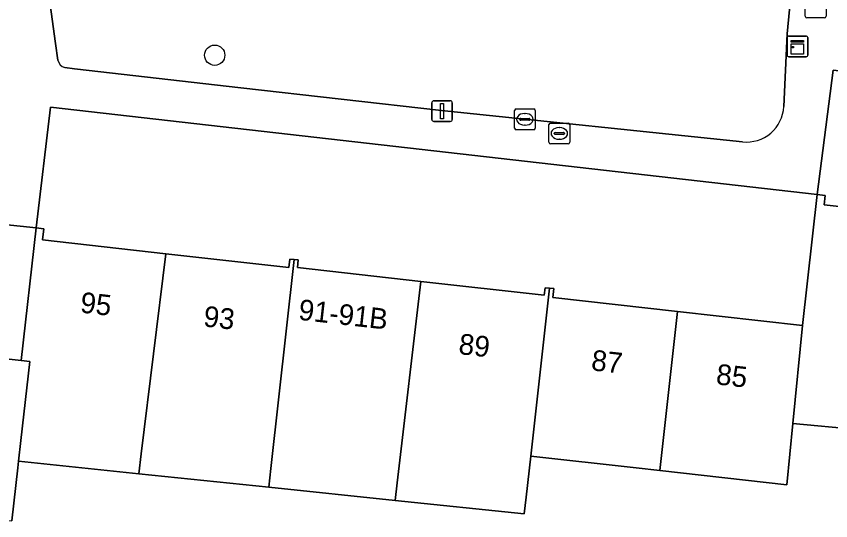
# Model space of a CAD drawing. Extents: x 162026 to 163502, y 387295 to 388169.
# Drawn here: x 162441.8 to 162481.07, y 387497.45 to 387521.8 of the extents above; entities that cross this region are included whole.
import ezdxf

# ---------------------------------------------------------------- set-up
doc = ezdxf.new("R2010")
doc.units = 0
for name, color, linetype in [('IMGEO_Boom', 7, 'Continuous'), ('IMGEO_Brandkraan', 7, 'Continuous'), ('IMGEO_Erf', 7, 'Continuous'), ('IMGEO_Groenvoorziening', 7, 'Continuous'), ('IMGEO_Kast', 7, 'Continuous'), ('IMGEO_Kolk', 7, 'Continuous'), ('IMGEO_Lichtmast', 7, 'Continuous'), ('IMGEO_Pand', 7, 'Continuous'), ('IMGEO_Pand_nummerreeks', 7, 'Continuous'), ('IMGEO_Rioolput', 7, 'Continuous'), ('IMGEO_Voetpad_open', 7, 'Continuous')]:
    doc.layers.add(name, color=color, linetype=linetype)

msp = doc.modelspace()

# ---------------------------------------------------------------- linework, layer by layer
at = {"layer": 'IMGEO_Boom'}
msp.add_circle((162451.365, 387519.921), 0.489, dxfattribs=at)
at = {"layer": 'IMGEO_Brandkraan'}
for p, q in [((162467.56, 387516.645), (162468.412, 387516.645)), ((162467.485, 387515.719), (162467.485, 387516.571)), ((162467.973, 387516.425), (162467.998, 387516.425)), ((162468.486, 387516.571), (162468.486, 387515.719)), ((162467.744, 387516.139), (162467.744, 387516.151)), ((162468.182, 387516.102), (162467.784, 387516.102)), ((162467.787, 387516.188), (162468.185, 387516.188)), ((162467.996, 387515.865), (162467.971, 387515.865)), ((162468.228, 387516.151), (162468.228, 387516.139)), ((162468.412, 387515.645), (162467.56, 387515.645))]:
    msp.add_line(p, q, dxfattribs=at)
for points in [[(162467.56, 387516.645), (162468.412, 387516.645)], [(162467.485, 387515.719), (162467.485, 387516.571)], [(162468.486, 387516.571), (162468.486, 387515.719)], [(162468.412, 387515.645), (162467.56, 387515.645)]]:
    msp.add_lwpolyline(points, dxfattribs=at)
for centre, radius, start, end in [((162467.562, 387516.569), 0.0765, 91.552, 178.448), ((162467.562, 387516.569), 0.0765, 91.552, 178.448), ((162468.41, 387516.569), 0.0765, 1.552, 88.448), ((162468.41, 387516.569), 0.0765, 1.552, 88.448), ((162467.784, 387516.148), 0.0403, 85.8775, 175.7526), ((162467.781, 387516.138), 0.0366, 178.938, 274.7102), ((162468.185, 387516.145), 0.043, 264.8664, 352.4533), ((162468.189, 387516.15), 0.0386, 1.7309, 96.639), ((162467.562, 387515.721), 0.0765, 181.552, 268.448), ((162467.562, 387515.721), 0.0765, 181.552, 268.448), ((162468.41, 387515.721), 0.0765, 271.552, 358.448), ((162468.41, 387515.721), 0.0765, 271.552, 358.448)]:
    msp.add_arc(centre, radius, start, end, dxfattribs=at)
for centre, major_axis, ratio, start_param, end_param in [((162467.972, 387516.145), (-0.387, 0.002), 0.722429, 4.712389, 7.853982), ((162467.997, 387516.145), (-0.39, 0.002), 0.717154, 1.570796, 4.712389)]:
    msp.add_ellipse(centre, major_axis=major_axis, ratio=ratio, start_param=start_param, end_param=end_param, dxfattribs=at)
at = {"layer": 'IMGEO_Erf'}
for points in [[(162518.432, 387515.192), (162500, 387517.178), (162481.197, 387519.204), (162480.419, 387513.193), (162480.812, 387513.149), (162480.763, 387512.704), (162486.71, 387512.041), (162492.656, 387511.378), (162492.721, 387511.96), (162492.85, 387511.945), (162492.978, 387511.931), (162492.934, 387511.542), (162498.912, 387510.875), (162500, 387510.754), (162504.89, 387510.209), (162504.952, 387510.769), (162505.14, 387510.748), (162505.332, 387510.727), (162505.29, 387510.35), (162511.235, 387509.687)], [(162436.195, 387505.838), (162442.029, 387505.182), (162442.75, 387511.59), (162411.844, 387514.804)], [(162510.383, 387502.006), (162504.247, 387502.69), (162500, 387503.163), (162498.081, 387503.377), (162491.976, 387504.058), (162491.538, 387500.106), (162487.162, 387500.516), (162487.274, 387501.717), (162485.483, 387501.885), (162485.453, 387501.561), (162479.244, 387502.144), (162478.95, 387499.184), (162472.84, 387499.871), (162471.696, 387500), (162466.61, 387500.572), (162466.385, 387498.59), (162466.293, 387497.784), (162460.067, 387498.432), (162453.973, 387499.067), (162447.706, 387499.72), (162441.91, 387500.323), (162441.874, 387500), (162441.588, 387497.454)]]:
    msp.add_lwpolyline(points, dxfattribs=at)
msp.add_lwpolyline([(162442.75, 387511.59), (162443.125, 387511.547), (162443.064, 387511.006), (162449.008, 387510.337), (162454.948, 387509.669), (162454.995, 387510.085), (162455.198, 387510.062), (162455.399, 387510.04), (162455.358, 387509.674), (162461.31, 387509.004), (162467.26, 387508.335), (162467.301, 387508.701), (162467.508, 387508.677), (162467.715, 387508.654), (162467.666, 387508.223), (162473.69, 387507.546), (162479.714, 387506.868), (162480.419, 387513.193), (162443.453, 387517.421)], close=True, dxfattribs=at)
at = {"layer": 'IMGEO_Groenvoorziening'}
for points in [[(162478.98, 387520.947), (162479.234, 387523.65), (162478.939, 387525.698), (162478.478, 387528.899), (162450.917, 387524.717), (162443.278, 387523.558), (162443.693, 387520.479), (162443.8, 387519.686)], [(162478.809, 387517.442), (162478.98, 387520.947)], [(162444.135, 387519.323), (162444.599, 387519.266), (162452.625, 387518.351), (162462.301, 387517.247), (162476.823, 387515.738)]]:
    msp.add_lwpolyline(points, dxfattribs=at)
for centre, radius, start, end in [((162444.266, 387519.78), 0.475, 191.3668, 254.0389), ((162477.009, 387517.53), 1.802, 264.063, 357.1966)]:
    msp.add_arc(centre, radius, start, end, dxfattribs=at)
at = {"layer": 'IMGEO_Kast'}
for p, q in [((162478.967, 387519.922), (162478.967, 387520.763)), ((162478.967, 387520.763), (162478.967, 387519.922)), ((162479.042, 387520.847), (162479.883, 387520.847)), ((162479.883, 387520.847), (162479.042, 387520.847)), ((162479.967, 387520.772), (162479.967, 387519.931)), ((162479.967, 387519.931), (162479.967, 387520.772)), ((162479.892, 387519.847), (162479.051, 387519.847)), ((162479.051, 387519.847), (162479.892, 387519.847))]:
    msp.add_line(p, q, dxfattribs=at)
for points in [[(162479.162, 387520.637), (162479.762, 387520.637), (162479.762, 387520.552), (162479.162, 387520.552), (162479.162, 387520.637)], [(162479.162, 387520.462), (162479.762, 387520.462), (162479.762, 387519.973), (162479.162, 387519.973), (162479.162, 387520.462)]]:
    msp.add_lwpolyline(points, dxfattribs=at)
msp.add_circle((162479.246, 387520.311), 0.0377, dxfattribs=at)
for centre, start, end in [((162479.045, 387520.769), 92.4484, 184.2845), ((162479.045, 387520.769), 92.4484, 184.2845), ((162479.889, 387520.769), 2.4484, 94.2845), ((162479.889, 387520.769), 2.4484, 94.2845), ((162479.045, 387519.925), 182.4484, 274.2845), ((162479.045, 387519.925), 182.4484, 274.2845), ((162479.889, 387519.925), 272.4484, 4.2845), ((162479.889, 387519.925), 272.4484, 4.2845)]:
    msp.add_arc(centre, 0.0779, start, end, dxfattribs=at)
at = {"layer": 'IMGEO_Kolk'}
for p, q in [((162465.826, 387516.401), (162465.826, 387517.253)), ((162465.901, 387517.327), (162466.753, 387517.327)), ((162466.314, 387517.107), (162466.339, 387517.107)), ((162466.827, 387517.253), (162466.827, 387516.401)), ((162466.085, 387516.821), (162466.085, 387516.833)), ((162466.523, 387516.784), (162466.125, 387516.784)), ((162466.128, 387516.87), (162466.526, 387516.87)), ((162466.569, 387516.833), (162466.569, 387516.821)), ((162466.753, 387516.327), (162465.901, 387516.327)), ((162466.337, 387516.547), (162466.312, 387516.547))]:
    msp.add_line(p, q, dxfattribs=at)
for points in [[(162465.826, 387516.401), (162465.826, 387517.253)], [(162465.901, 387517.327), (162466.753, 387517.327)], [(162466.827, 387517.253), (162466.827, 387516.401)], [(162466.753, 387516.327), (162465.901, 387516.327)]]:
    msp.add_lwpolyline(points, dxfattribs=at)
for centre, radius, start, end in [((162465.903, 387517.251), 0.0765, 91.552, 178.448), ((162465.903, 387517.251), 0.0765, 91.552, 178.448), ((162466.751, 387517.251), 0.0765, 1.552, 88.448), ((162466.751, 387517.251), 0.0765, 1.552, 88.448), ((162466.125, 387516.83), 0.0403, 85.8775, 175.7526), ((162466.122, 387516.82), 0.0366, 178.938, 274.7102), ((162466.526, 387516.827), 0.043, 264.8664, 352.4533), ((162466.53, 387516.832), 0.0386, 1.7309, 96.639), ((162465.903, 387516.403), 0.0765, 181.552, 268.448), ((162465.903, 387516.403), 0.0765, 181.552, 268.448), ((162466.751, 387516.403), 0.0765, 271.552, 358.448), ((162466.751, 387516.403), 0.0765, 271.552, 358.448)]:
    msp.add_arc(centre, radius, start, end, dxfattribs=at)
for centre, major_axis, ratio, start_param, end_param in [((162466.313, 387516.827), (-0.387, 0.002), 0.722429, 4.712389, 7.853982), ((162466.338, 387516.827), (-0.39, 0.002), 0.717154, 1.570796, 4.712389)]:
    msp.add_ellipse(centre, major_axis=major_axis, ratio=ratio, start_param=start_param, end_param=end_param, dxfattribs=at)
at = {"layer": 'IMGEO_Lichtmast'}
for p, q in [((162461.834, 387516.823), (162461.834, 387517.623)), ((162461.834, 387517.623), (162461.834, 387516.823)), ((162461.934, 387517.723), (162462.724, 387517.723)), ((162462.724, 387517.723), (162461.934, 387517.723)), ((162462.824, 387517.623), (162462.824, 387516.823)), ((162462.824, 387516.823), (162462.824, 387517.623)), ((162462.724, 387516.723), (162461.934, 387516.723)), ((162461.934, 387516.723), (162462.724, 387516.723))]:
    msp.add_line(p, q, dxfattribs=at)
msp.add_lwpolyline([(162462.254, 387517.598), (162462.404, 387517.598), (162462.404, 387516.848), (162462.254, 387516.848), (162462.254, 387517.598)], dxfattribs=at)
for centre, start, end in [((162461.934, 387517.623), 90, 180), ((162461.934, 387517.623), 90, 180), ((162462.724, 387517.623), 0, 90), ((162462.724, 387517.623), 360, 90), ((162461.934, 387516.823), 180, 270), ((162461.934, 387516.823), 180, 270), ((162462.724, 387516.823), 270, 0), ((162462.724, 387516.823), 270, 0)]:
    msp.add_arc(centre, 0.1, start, end, dxfattribs=at)
at = {"layer": 'IMGEO_Pand'}
for points in [[(162486.71, 387512.041), (162480.763, 387512.704), (162480.812, 387513.149), (162480.419, 387513.193), (162479.714, 387506.868), (162479.244, 387502.144), (162485.453, 387501.561), (162485.483, 387501.885)], [(162449.008, 387510.337), (162443.064, 387511.006), (162443.125, 387511.547), (162442.75, 387511.59), (162442.029, 387505.182), (162442.451, 387505.135), (162442.023, 387501.328), (162441.91, 387500.323), (162447.706, 387499.72), (162447.823, 387500.676)], [(162455.198, 387510.062), (162454.995, 387510.085), (162454.948, 387509.669), (162449.008, 387510.337), (162447.823, 387500.676), (162447.706, 387499.72), (162453.973, 387499.067), (162454.08, 387499.972)], [(162461.31, 387509.004), (162455.358, 387509.674), (162455.399, 387510.04), (162455.198, 387510.062), (162454.08, 387499.972), (162453.973, 387499.067), (162460.067, 387498.432), (162460.168, 387499.288)], [(162467.508, 387508.677), (162467.301, 387508.701), (162467.26, 387508.335), (162461.31, 387509.004), (162460.168, 387499.288), (162460.067, 387498.432), (162466.293, 387497.784), (162466.385, 387498.59), (162466.61, 387500.572)], [(162466.61, 387500.572), (162471.696, 387500), (162472.84, 387499.871), (162473.69, 387507.546), (162467.666, 387508.223), (162467.715, 387508.654), (162467.508, 387508.677)], [(162479.714, 387506.868), (162473.69, 387507.546), (162472.84, 387499.871), (162478.95, 387499.184), (162479.244, 387502.144)], [(162442.451, 387505.135), (162442.029, 387505.182), (162436.195, 387505.838), (162435.549, 387500.001), (162435.345, 387498.156), (162441.588, 387497.454), (162441.874, 387500), (162441.91, 387500.323), (162442.023, 387501.328)]]:
    msp.add_lwpolyline(points, close=True, dxfattribs=at)
at = {"layer": 'IMGEO_Rioolput'}
for p, q in [((162479.847, 387521.8), (162479.847, 387522.652)), ((162480.848, 387522.652), (162480.848, 387521.8)), ((162480.774, 387521.726), (162479.922, 387521.726))]:
    msp.add_line(p, q, dxfattribs=at)
for points in [[(162479.847, 387521.8), (162479.847, 387522.652)], [(162480.848, 387522.652), (162480.848, 387521.8)], [(162480.774, 387521.726), (162479.922, 387521.726)]]:
    msp.add_lwpolyline(points, dxfattribs=at)
for centre, start, end in [((162479.924, 387521.802), 181.552, 268.448), ((162479.924, 387521.802), 181.552, 268.448), ((162480.772, 387521.802), 271.552, 358.448), ((162480.772, 387521.802), 271.552, 358.448)]:
    msp.add_arc(centre, 0.0765, start, end, dxfattribs=at)
at = {"layer": 'IMGEO_Voetpad_open'}
for points in [[(162443.278, 387523.558), (162450.917, 387524.717), (162478.478, 387528.899), (162478.939, 387525.698), (162479.234, 387523.65), (162478.98, 387520.947), (162478.809, 387517.442)], [(162443.8, 387519.686), (162443.693, 387520.479), (162443.278, 387523.558)], [(162383.865, 387511.154), (162385.791, 387511.457), (162404.551, 387514.406), (162408.822, 387515.078), (162409.124, 387515.071), (162411.844, 387514.804), (162442.75, 387511.59), (162443.453, 387517.421), (162480.419, 387513.193), (162481.197, 387519.204), (162500, 387517.178), (162518.432, 387515.192)], [(162476.823, 387515.738), (162462.301, 387517.247), (162452.625, 387518.351), (162444.599, 387519.266), (162444.135, 387519.323)]]:
    msp.add_lwpolyline(points, dxfattribs=at)
for centre, radius, start, end in [((162444.266, 387519.78), 0.475, 191.3668, 254.0389), ((162477.009, 387517.53), 1.802, 264.063, 357.1966)]:
    msp.add_arc(centre, radius, start, end, dxfattribs=at)

# ---------------------------------------------------------------- texts
at = {"layer": 'IMGEO_Pand_nummerreeks'}
for s, rotation, p in [('95', 353.5771, (162444.848, 387507.505)), ('91-91B', 353.5771, (162455.373, 387507.157)), ('93', 353.5829, (162450.791, 387506.836)), ('89', 353.5771, (162463.096, 387505.503)), ('87', 353.5972, (162469.492, 387504.718)), ('85', 353.5714, (162475.513, 387504.04))]:
    msp.add_text(s, height=1, rotation=rotation, dxfattribs=at).set_placement(p)

doc.saveas('drawing.dxf')
